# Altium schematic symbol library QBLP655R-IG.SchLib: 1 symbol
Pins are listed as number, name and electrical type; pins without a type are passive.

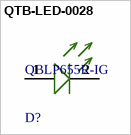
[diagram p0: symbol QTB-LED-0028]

## QTB-LED-0028
designator D?, comment QBLP655R-IG
LED GREEN CLEAR 1205 SMD, REVERSE MOUNT; Manufacturer: QT Brightek (QTB); Lens Size: 1.2mm; Luminous Intensity: 525mcd; Test Current: 20mA; Lens Color: Colorless; Lens Style: Square with Flat Top; Forward Voltage: 3.1V; Wavelength - Dominant: 520nm; Viewing Angle: 140º
footprint QBLP655R-IG
pins: 1 ANODE (+), 2 CATHODE (-)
